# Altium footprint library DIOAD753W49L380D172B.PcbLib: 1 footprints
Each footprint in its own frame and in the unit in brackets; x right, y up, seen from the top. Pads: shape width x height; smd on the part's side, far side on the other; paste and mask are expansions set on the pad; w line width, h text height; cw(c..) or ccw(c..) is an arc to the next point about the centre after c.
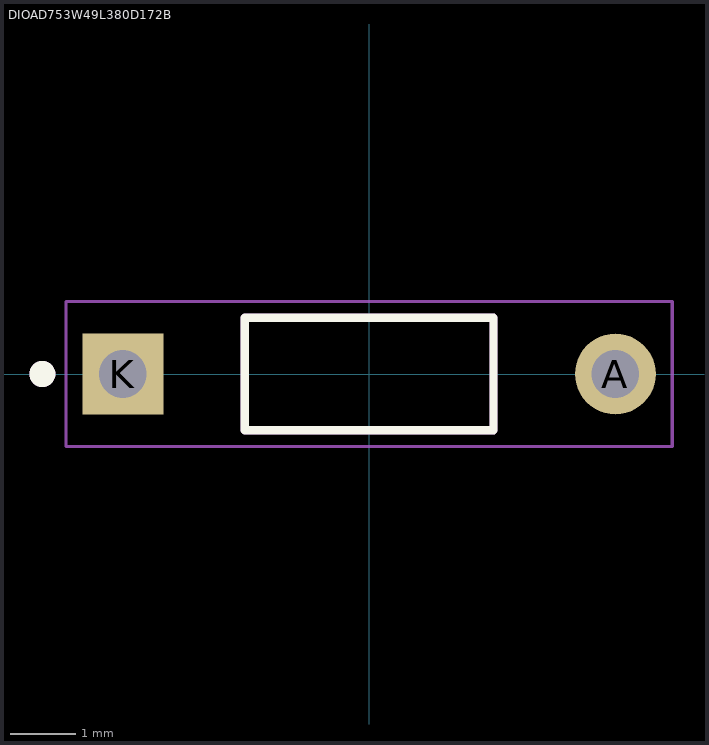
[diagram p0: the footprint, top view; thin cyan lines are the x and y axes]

## DIOAD753W49L380D172B [mm]
height 1.91
pads (2):
  round 1.238 hole 0.73 mask+0.102: A(3.768,0)
  rect 1.238x1.238 / inner round 1.238 / far side rect 1.238x1.238 hole 0.73 mask+0.102: K(-3.768,0)
Top Overlay:
  circle w0.2: c-5,0 r0.1
  lines w0.127: -1.903,-0.86 1.903,-0.86 1.903,0.86 -1.903,0.86 -1.903,-0.86
Assembly Top:
  circle w0.2: c-5,0 r0.1
  lines w0.127: -1.903,-0.86 1.903,-0.86 1.903,0.86 -1.903,0.86 -1.903,-0.86
Courtyard Top:
  lines w0.05: -4.637,-1.11 4.637,-1.11 4.637,1.11 -4.637,1.11 -4.637,-1.11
